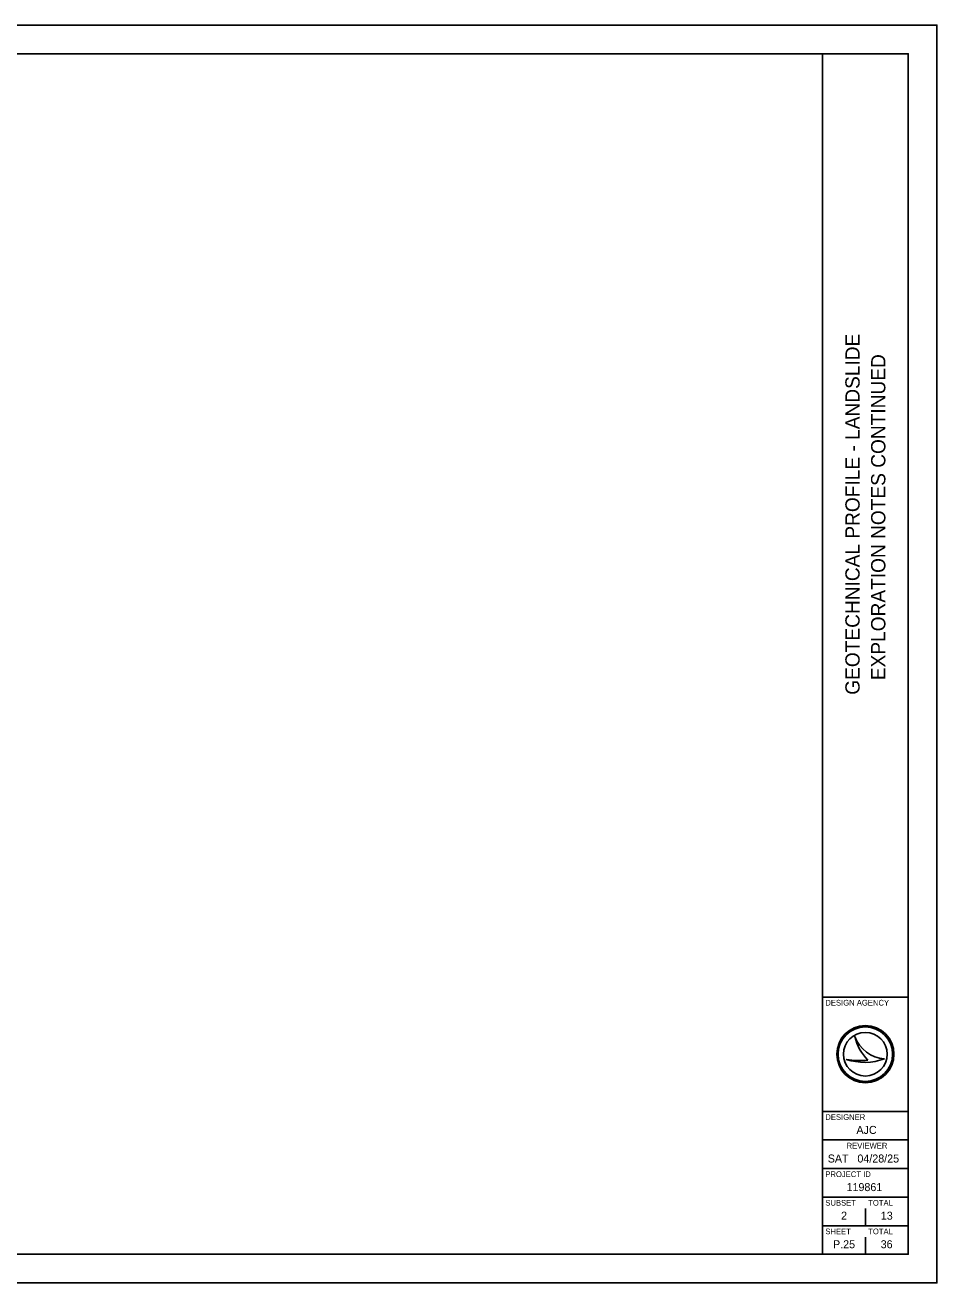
# Model space of a CAD drawing. Extents: x 0 to 34, y 0 to 22.
# Drawn here: x 18.06 to 34, y 0 to 22 of the extents above; entities that cross this region are included whole.
import ezdxf

# ---------------------------------------------------------------- set-up
doc = ezdxf.new("R2010")
doc.units = 0
for name, color, linetype in [('SH_Border', 7, 'Continuous'), ('SH_Cut_Line', 7, 'Continuous'), ('SH_Data', 7, 'Continuous')]:
    doc.layers.add(name, color=color, linetype=linetype)

msp = doc.modelspace()

# ---------------------------------------------------------------- linework, layer by layer
at = {"layer": 'SH_Border'}
for p, q in [((32, 0.5), (32, 21.5)), ((32, 5), (33.5, 5)), ((32, 3), (33.5, 3)), ((32, 2.5), (33.5, 2.5)), ((32, 2), (33.5, 2)), ((32, 1.5), (33.5, 1.5)), ((32, 1), (33.5, 1))]:
    msp.add_line(p, q, dxfattribs=at)
msp.add_lwpolyline([(1.5, 21.5), (33.5, 21.5), (33.5, 0.5), (1.5, 0.5)], close=True, dxfattribs=at)
at = {"layer": 'SH_Cut_Line'}
msp.add_lwpolyline([(0, 0), (34, 0), (34, 22), (0, 22)], close=True, dxfattribs=at)
at = {"layer": 'SH_Data'}
for p, q in [((32.567, 4.31), (32.567, 4.31)), ((32.75, 4), (32.75, 4)), ((32.417, 3.91), (32.417, 3.91)), ((33.087, 3.919), (33.087, 3.919)), ((32.75, 1), (32.75, 1.3)), ((32.375, 0.675), (32.375, 0.675)), ((32.75, 0.5), (32.75, 0.8))]:
    msp.add_line(p, q, dxfattribs=at)
for radius in [0.5, 0.477, 0.477, 0.382]:
    msp.add_circle((32.75, 4), radius, dxfattribs=at)
for centre, radius, start, end in [((33.116, 4.498), 0.58, 198.9257, 198.9319), ((33.347, 4.47), 0.796, 191.6379, 191.6421), ((33.116, 4.498), 0.58, 198.9319, 267.1657), ((33.347, 4.47), 0.796, 191.6421, 226.0947), ((32.739, 4.87), 1.013, 251.4576, 290.0832), ((32.648, 5.154), 1.266, 259.4964, 259.4995), ((32.739, 4.87), 1.013, 251.4527, 251.4576), ((32.648, 5.154), 1.266, 259.4995, 276.6672)]:
    msp.add_arc(centre, radius, start, end, dxfattribs=at)

# ---------------------------------------------------------------- texts
for s, p in [('GEOTECHNICAL PROFILE - LANDSLIDE', (32.65, 10.287)), ('EXPLORATION NOTES CONTINUED', (33.1, 10.542))]:
    msp.add_text(s, height=0.25, rotation=90, dxfattribs=at).set_placement(p)
for s, height, p in [('DESIGN AGENCY', 0.1, (32.05, 4.85)), ('DESIGNER', 0.1, (32.05, 2.85)), ('AJC', 0.14, (32.594, 2.605)), ('REVIEWER', 0.1, (32.422, 2.35)), ('SAT', 0.14, (32.092, 2.105)), ('04/28/25', 0.14, (32.611, 2.105)), ('PROJECT ID', 0.1, (32.05, 1.85)), ('119861', 0.14, (32.421, 1.605)), ('SUBSET', 0.1, (32.05, 1.35)), ('TOTAL', 0.1, (32.8, 1.35)), ('2', 0.14, (32.325, 1.105)), ('13', 0.14, (33.02, 1.105)), ('SHEET', 0.1, (32.05, 0.85)), ('TOTAL', 0.1, (32.8, 0.85)), ('P.25', 0.14, (32.185, 0.605)), ('36', 0.14, (33.018, 0.605))]:
    msp.add_text(s, height=height, dxfattribs=at).set_placement(p)

doc.saveas('drawing.dxf')
